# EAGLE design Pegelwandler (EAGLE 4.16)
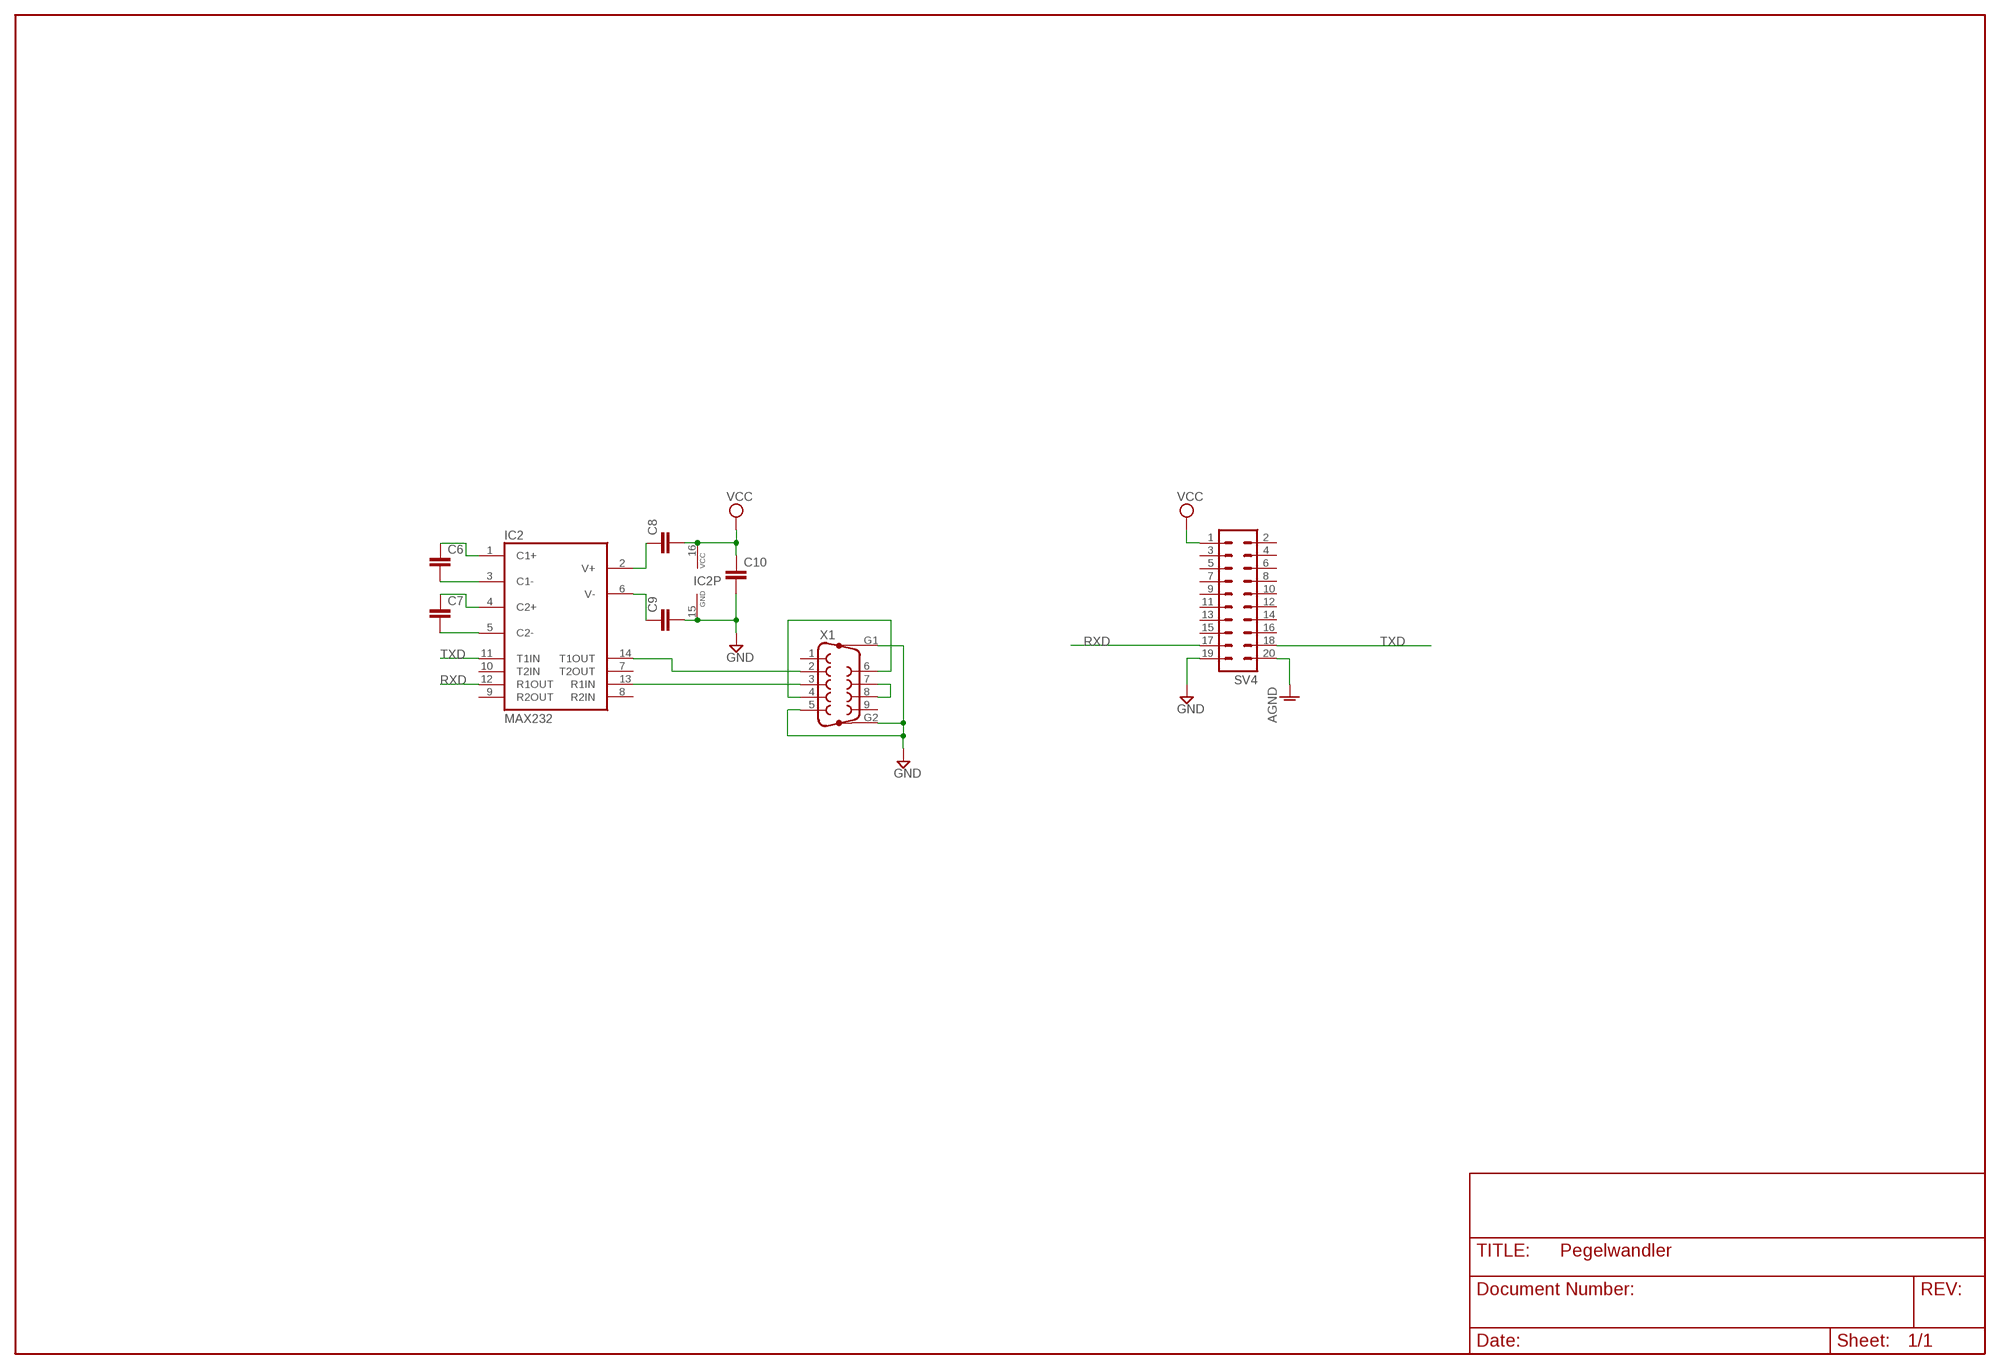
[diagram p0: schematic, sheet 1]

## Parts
C6  C-EUC1206K  [C1206K]
C7  C-EUC1206K  [C1206K]
C8  C-EUC1206K  [C1206K]
C9  C-EUC1206K  [C1206K]
C10  C-EUC1206K  [C1206K]
IC2  MAX232  [DIL16]
SV4  ML20  [ML20]
X1  F09HP  [F09HP]

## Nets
AGND: SV4.20
GND: C9.2 C10.2 IC2.15(GND) SV4.19 X1.5 X1.G1 X1.G2
N$5: IC2.13(R1IN) X1.3
N$8: X1.4 X1.6
N$9: X1.7 X1.8
N$10: IC2.14(T1OUT) X1.2
N$25: C7.2 IC2.5(C2-)
N$26: C7.1 IC2.4(C2+)
N$27: C6.2 IC2.3(C1-)
N$28: C6.1 IC2.1(C1+)
N$30: C8.1 IC2.2(V+)
N$31: C9.1 IC2.6(V-)
RXD: IC2.12(R1OUT) SV4.17
TXD: IC2.11(T1IN) SV4.18
VCC: C8.2 C10.1 IC2.16(VCC) SV4.1
Unconnected: IC2.7(T2OUT) IC2.8(R2IN) IC2.9(R2OUT) IC2.10(T2IN) SV4.2 SV4.3 SV4.4 SV4.5 SV4.6 SV4.7 SV4.8 SV4.9 SV4.10 SV4.11 SV4.12 SV4.13 SV4.14 SV4.15 SV4.16 X1.1 X1.9

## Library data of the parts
C6-C10 = rcl:C-EU: CAPACITOR, European symbol
IC2 = maxim:MAX232: RS232 TRANSEIVER
SV4 = con-harting-ml:ML20: HARTING
X1 = con-subd:F09HP: SUB-D

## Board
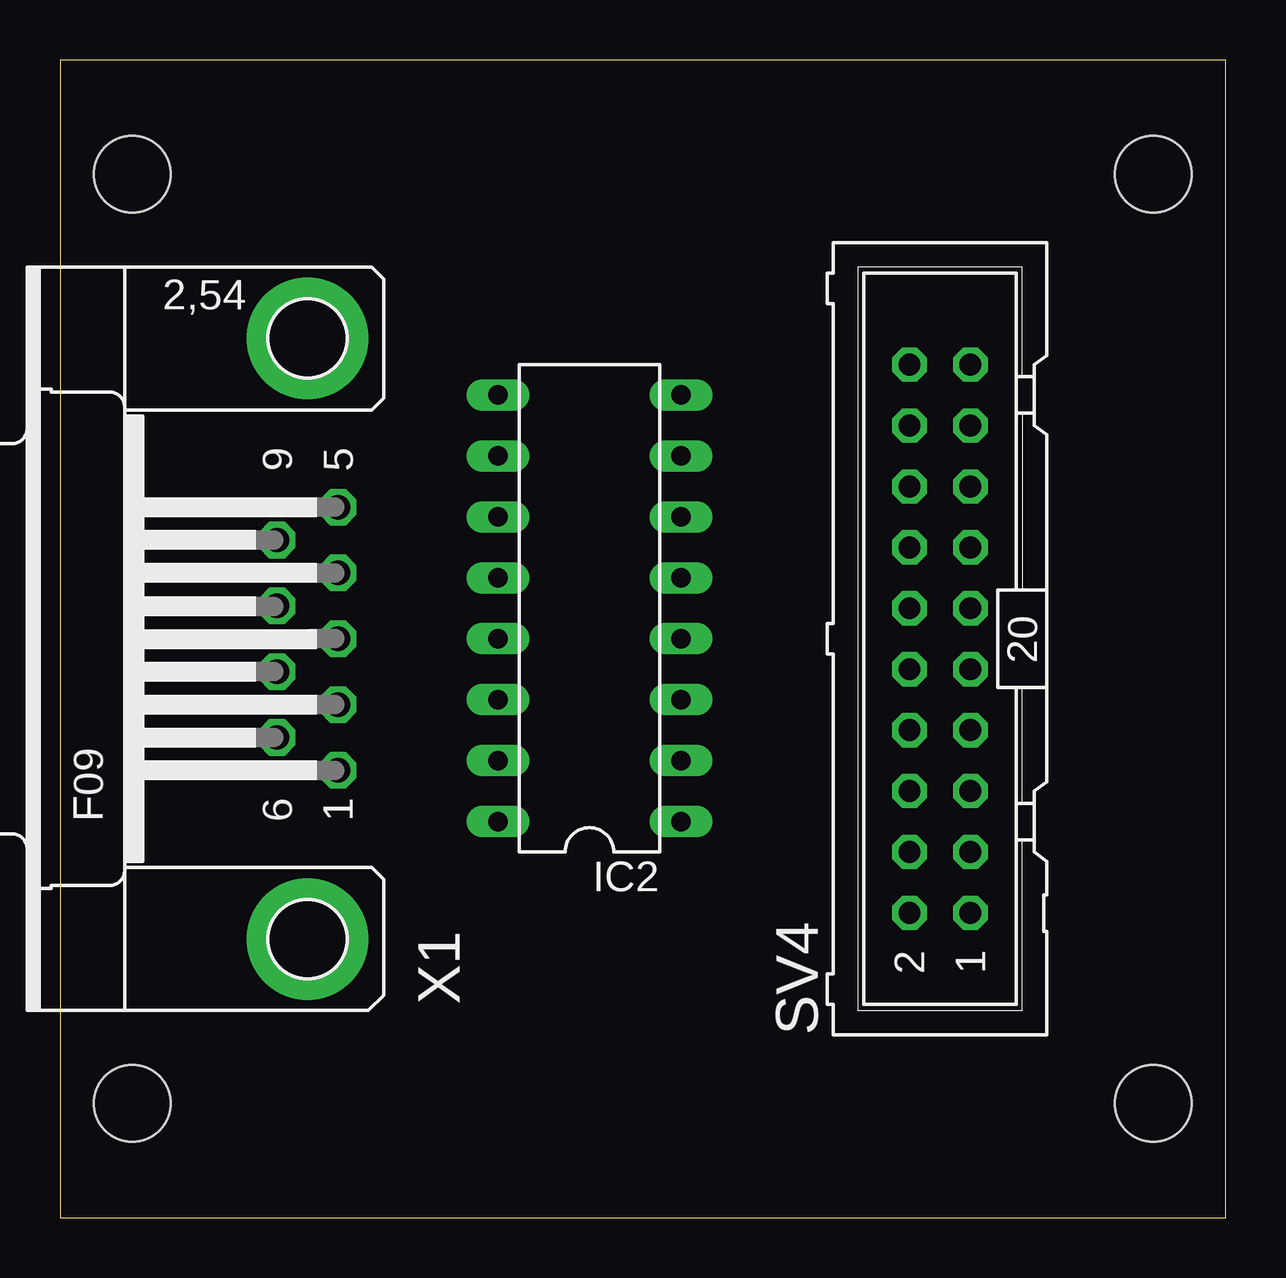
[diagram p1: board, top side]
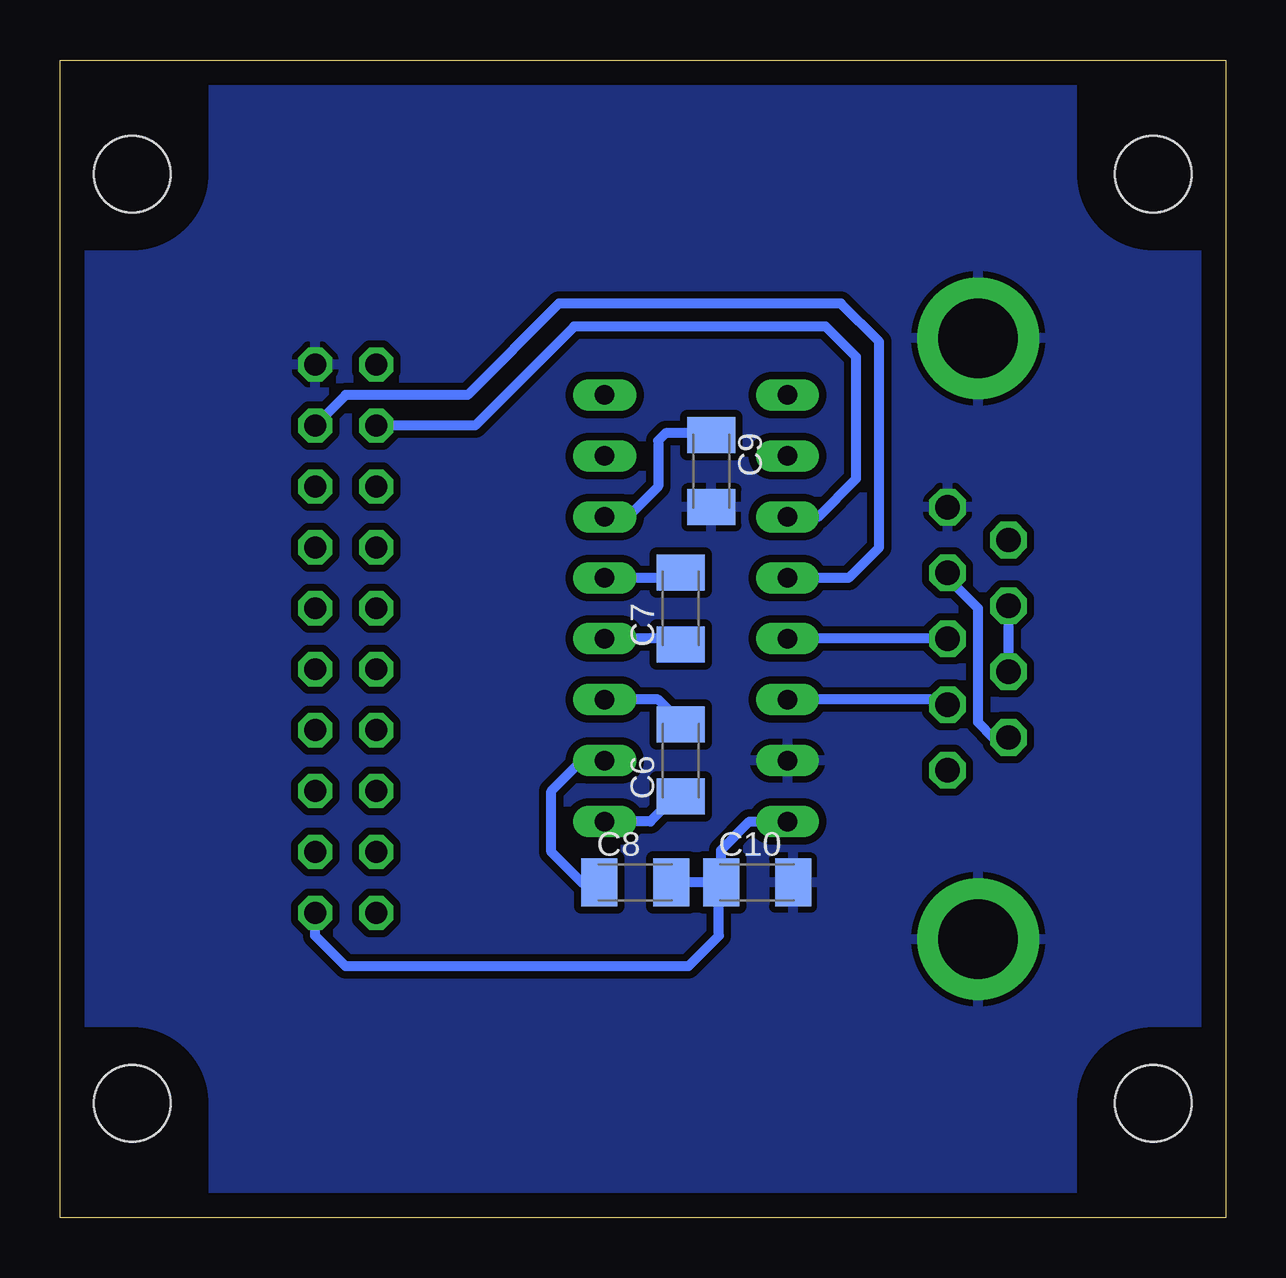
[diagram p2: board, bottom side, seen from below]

Size 48.56 x 48.25 mm. Coordinates in mm from the lower left corner, seen from the top.
Outline: 0,0 48.56,0 48.56,48.25 0,48.25 0,0
Copper layers (1*16): Top 0.035mm / dielectric 1.5mm / Bottom 0.035mm
Design rules "default": minimum track width 10mil, minimum drill 24mil, track to track 12mil, track to pad 12mil, pad to pad 12mil, via to via 12mil, smd to smd 12mil, copper to edge 40mil, drill to drill 8mil, minimum pad ring 10mil, minimum via ring 8mil, stop-mask expansion 4mil, vias tented up to drill 0mil, thermal gap 10mil
Holes 3.2 mm at 45.55,4.76 3.01,43.49 45.55,43.49 3.01,4.76
bRestrict: area -0.2,40.3 to 6.2,46.7; area 42.4,40.3 to 48.7,46.7; area 42.4,1.6 to 48.7,7.9; area -0.2,1.6 to 6.2,7.9; area 3,43.5 to 6.2,47.3; area 0.2,40.3 to 3,43.5; area -0.2,4.8 to 3,7.9; area 45.6,4.8 to 48.7,7.9; area 42.4,0.9 to 45.6,4.8; area 3,0.9 to 6.2,4.8; area 42.4,43.5 to 45.6,47.3; area 45.6,40.3 to 48.7,43.8

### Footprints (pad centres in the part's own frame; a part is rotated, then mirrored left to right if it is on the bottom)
C1206K = smd 1.5 x 2: 1 -1.5,0; 2 1.5,0
DIL16 = drill 0.813 long: 1 -8.89,-3.81; 2 -6.35,-3.81; 3 -3.81,-3.81; 4 -1.27,-3.81; 5 1.27,-3.81; 6 3.81,-3.81; 7 6.35,-3.81; 8 8.89,-3.81; 9 8.89,3.81; 10 6.35,3.81; 11 3.81,3.81; 12 1.27,3.81; 13 -1.27,3.81; 14 -3.81,3.81; 15 -6.35,3.81; 16 -8.89,3.81
ML20 = drill 0.914 octagon: 1 -11.43,-1.27; 2 -11.43,1.27; 3 -8.89,-1.27; 4 -8.89,1.27; 5 -6.35,-1.27; 6 -6.35,1.27; 7 -3.81,-1.27; 8 -3.81,1.27; 9 -1.27,-1.27; 10 -1.27,1.27; 11 1.27,-1.27; 12 1.27,1.27; 13 3.81,-1.27; 14 3.81,1.27; 15 6.35,-1.27; 16 6.35,1.27; 17 8.89,-1.27; 18 8.89,1.27; 19 11.43,-1.27; 20 11.43,1.27
F09HP = drill 1.016 octagon: 1 -5.486,-1.27; 2 -2.743,-1.27; 3 0,-1.27; 4 2.743,-1.27; 5 5.486,-1.27; 6 -4.115,1.27; 7 -1.372,1.27; 8 1.372,1.27; 9 4.115,1.27 | drill 3.302 pad 5.08 round: G1 -12.522,0; G2 12.522,0

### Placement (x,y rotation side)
C6  22.7,19.04 90 bottom
C7  22.7,25.39 90 bottom
C8  24.6,13.96 0 bottom
C9  21.43,31.11 270 bottom
C10  19.52,13.96 0 bottom
IC2  22.06,25.39 90 top
SV4  36.66,24.12 90 top
X1  10.31,24.12 90 top

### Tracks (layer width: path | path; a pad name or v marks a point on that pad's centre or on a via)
GND
  pour Bottom: 0.15,48.26 48.41,48.26 48.41,0 0.15,0
N$5
  Bottom 0.406: X1.3 IC2.13
N$8
  Bottom 0.406: X1.6 9.68,20 10.31,20.65 10.31,25.4 11.58,26.66 X1.4
N$9
  Bottom 0.406: X1.7 X1.8
N$10
  Bottom 0.406: X1.2 11.58,21.59 IC2.14
N$25
  Bottom 0.406: C7.2 22.7,26.98 23.01,26.66 IC2.5
N$26
  Bottom 0.406: C7.1 22.7,23.81 23.01,24.13 IC2.4
N$27
  Bottom 0.406: C6.2 22.7,20.63 23.65,21.59 IC2.3
N$28
  Bottom 0.406: C6.1 22.93,17.54 23.96,16.5 IC2.1
N$30
  Bottom 0.406: IC2.2 26.82,19.04 28.09,17.77 28.09,15.24 26.82,13.97 C8.1 25.87,13.97
N$31
  Bottom 0.406: IC2.6 24.92,29.21 23.65,30.47 23.65,32.38 23.33,32.7 21.74,32.7 21.66,32.61 C9.1
RXD
  Bottom 0.406: IC2.12 15.71,26.66 14.44,27.93 14.44,36.51 16.03,38.1 27.77,38.1 31.59,34.29 36.66,34.29 SV4.17
TXD
  Bottom 0.406: SV4.18 31.27,33.01 27.14,37.14 16.66,37.14 15.39,35.87 15.39,30.79 16.98,29.21 IC2.11
VCC
  Bottom 0.406: 23.33,13.97 C8.2 21.11,13.97 | IC2.16 19.84,16.5 21.02,15.32 C10.1 21.11,13.97 | SV4.1 37.94,11.74 36.66,10.47 22.38,10.47 21.11,11.74 21.11,13.97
